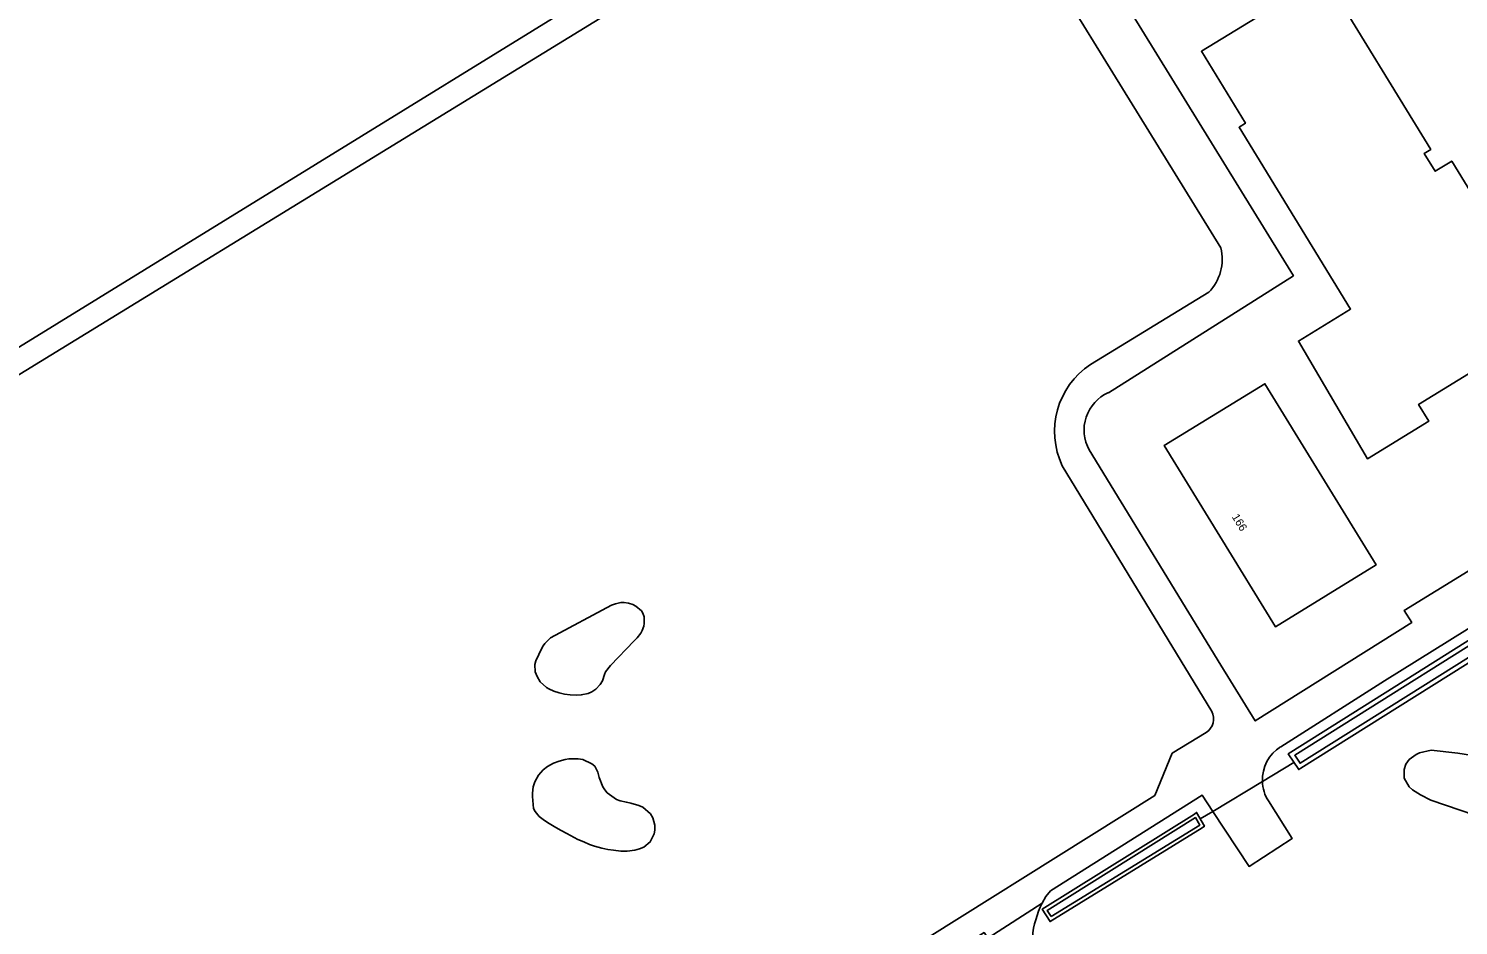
# Model space of a CAD drawing. Extents: x 156061 to 157804, y 383437 to 385640.
# Drawn here: x 157310.1 to 157488.8, y 384302.2 to 384414.3 of the extents above; entities that cross this region are included whole.
import ezdxf

# ---------------------------------------------------------------- set-up
doc = ezdxf.new("R2010")
doc.units = 0
for name, color, linetype in [('IMGEO_Duiker', 7, 'Continuous'), ('IMGEO_Groenvoorziening', 7, 'Continuous'), ('IMGEO_Oever', 7, 'Continuous'), ('IMGEO_Pand', 7, 'Continuous'), ('IMGEO_Pand_nummerreeks', 7, 'Continuous'), ('IMGEO_Parkeervlak_open', 7, 'Continuous'), ('IMGEO_Rijbaan_lokaal_open', 7, 'Continuous'), ('IMGEO_Terreindeel_zand', 7, 'Continuous'), ('IMGEO_Waterloop', 7, 'Continuous')]:
    doc.layers.add(name, color=color, linetype=linetype)

msp = doc.modelspace()

# ---------------------------------------------------------------- linework, layer by layer
at = {"layer": 'IMGEO_Duiker'}
msp.add_lwpolyline([(157468.24, 384322.62), (157464.32, 384320.24), (157458.11, 384316.49), (157456.56, 384315.56)], dxfattribs=at)
at = {"layer": 'IMGEO_Groenvoorziening'}
for points in [[(157422.9, 384440.97), (157244.99, 384331.9), (157233.07, 384324.81), (157231.44, 384327.44), (157263.86, 384346.91), (157291.7, 384363.94), (157433.08, 384451.02), (157463.89, 384469.64), (157500, 384491.86)], [(157459.14, 384386.91), (157426.43, 384439.93)], [(157434.04, 384438.87), (157468.2, 384383.43), (157445.07, 384368.81)], [(157442.82, 384372.34), (157457.62, 384381.36)], [(157442.68, 384361.66), (157459.13, 384334.77), (157463.42, 384327.8), (157482.98, 384340.1), (157482.05, 384341.61), (157490.03, 384346.53)], [(157457.99, 384328.99), (157439.3, 384359.67)], [(157500, 384345.51), (157479.57, 384332.82), (157466.6, 384324.58)], [(157422.28, 384264.72), (157416.27, 384274.39), (157438.11, 384288.09), (157430, 384300.64), (157429.54, 384301.35), (157347.95, 384250), (157322.66, 384234.08), (157320.89, 384236.78), (157341.5, 384250), (157450.86, 384318.47), (157453.06, 384323.75), (157457.3, 384326.36)], [(157490.88, 384316.01), (157485.38, 384317.89), (157484.06, 384318.55), (157483.07, 384319.2), (157482.68, 384319.57), (157482.05, 384320.66), (157482.02, 384321.74), (157482.26, 384322.38), (157482.67, 384322.96), (157483.52, 384323.61), (157483.93, 384323.81), (157485.4, 384324.14), (157488.74, 384323.78), (157491.37, 384323.35)], [(157465.07, 384317.8), (157468.04, 384313.11), (157462.66, 384309.61), (157458.11, 384316.49), (157456.79, 384318.5), (157437.84, 384306.57), (157437.24, 384305.85), (157436.8, 384305.03)]]:
    msp.add_lwpolyline(points, dxfattribs=at)
for points in [[(157500, 384378.16), (157500.4, 384377.5), (157500, 384377.25), (157483.83, 384367.34), (157485.12, 384365.26), (157477.44, 384360.55), (157468.81, 384375.27), (157475.33, 384379.26), (157461.4, 384401.99), (157462.2, 384402.49), (157456.69, 384411.48), (157472.06, 384420.9), (157485.36, 384399.22), (157484.54, 384398.72), (157485.91, 384396.48), (157487.98, 384397.76)], [(157500, 384341.28), (157469.14, 384321.89), (157468.85, 384321.71), (157467.54, 384323.67), (157467.87, 384323.89), (157500, 384344.09), (157567.48, 384386.23), (157568.22, 384386.06), (157568.84, 384385.18), (157568.87, 384384.42)], [(157478.53, 384347.29), (157465.94, 384339.56), (157452.04, 384362.21), (157464.63, 384369.94)], [(157382.85, 384334.74), (157382.23, 384333.92), (157382.1, 384333.6), (157381.83, 384332.82), (157381.55, 384332.33), (157381.01, 384331.77), (157380.5, 384331.42), (157380.06, 384331.23), (157379.18, 384331.05), (157378.58, 384331.03), (157377.79, 384331.07), (157377.1, 384331.16), (157376.41, 384331.31), (157375.76, 384331.51), (157375.13, 384331.8), (157374.83, 384331.98), (157374.07, 384332.68), (157373.66, 384333.33), (157373.44, 384333.93), (157373.38, 384334.83), (157373.5, 384335.29), (157373.87, 384336.11), (157374.09, 384336.56), (157374.42, 384337.17), (157374.63, 384337.46), (157375.35, 384338.18), (157382.95, 384342.26), (157383.48, 384342.45), (157384.14, 384342.61), (157384.56, 384342.61), (157385.11, 384342.52), (157385.65, 384342.33), (157386.01, 384342.15), (157386.7, 384341.57), (157386.9, 384341.26), (157387.05, 384340.81), (157387.06, 384339.96), (157387, 384339.62), (157386.82, 384339.09), (157386.64, 384338.76), (157386.19, 384338.19), (157385.8, 384337.79)], [(157373.85, 384321), (157374.41, 384321.67), (157374.97, 384322.11), (157375.74, 384322.51), (157376.43, 384322.77), (157377.2, 384322.96), (157377.65, 384323.04), (157378.79, 384323.07), (157379.37, 384322.97), (157380.51, 384322.45), (157380.87, 384322.15), (157381.26, 384321.39), (157381.43, 384320.72), (157381.87, 384319.57), (157382.14, 384319.17), (157382.43, 384318.82), (157383.6, 384317.96), (157384.05, 384317.8), (157384.83, 384317.64), (157385.39, 384317.53), (157386.37, 384317.24), (157386.87, 384317.01), (157387.84, 384316.18), (157388.12, 384315.7), (157388.37, 384314.77), (157388.38, 384314.13), (157388.32, 384313.7), (157387.82, 384312.67), (157387, 384312.04), (157386.48, 384311.81), (157385.89, 384311.64), (157384.92, 384311.52), (157384.12, 384311.54), (157383.24, 384311.63), (157382.53, 384311.74), (157381.76, 384311.91), (157380.85, 384312.16), (157380.24, 384312.37), (157379.5, 384312.67), (157378.78, 384313), (157378.29, 384313.24), (157377.38, 384313.71), (157376.69, 384314.09), (157376, 384314.48), (157375.2, 384314.97), (157374.59, 384315.36), (157373.93, 384315.87), (157373.42, 384316.46), (157373.21, 384316.87), (157373.08, 384318.37), (157373.1, 384318.78), (157373.2, 384319.58), (157373.38, 384320.17)], [(157437.78, 384302.72), (157436.8, 384304.27), (157455.82, 384316.16), (157456.1, 384316.36), (157457.08, 384314.64), (157456.81, 384314.44)]]:
    msp.add_lwpolyline(points, close=True, dxfattribs=at)
for centre, radius, start, end in [((157453.3, 384385.53), 6, 316.0189, 13.3207), ((157448.38, 384363.97), 10.04, 123.5766, 205.3383), ((157447.14, 384364.15), 5.11, 113.9447, 209.1133), ((157456.24, 384328.05), 1.99, 302.1109, 28.211), ((157469.24, 384320.42), 4.93, 122.4518, 181.9995), ((157469.25, 384320.42), 4.94, 182.0776, 212.1015), ((157447.84, 384299.56), 12.33, 153.6448, 174.3328)]:
    msp.add_arc(centre, radius, start, end, dxfattribs=at)
at = {"layer": 'IMGEO_Oever'}
for points in [[(157568.87, 384384.42), (157568.84, 384385.18), (157568.22, 384386.06), (157567.48, 384386.23), (157500, 384344.09), (157467.87, 384323.89), (157467.54, 384323.67), (157468.85, 384321.71), (157469.14, 384321.89), (157500, 384341.28)], [(157567.37, 384385.48), (157567.83, 384385.42), (157568.11, 384385), (157568.11, 384384.62), (157499.69, 384341.77), (157469.02, 384322.5), (157468.35, 384323.51), (157500.31, 384343.59)], [(157456.81, 384314.44), (157457.08, 384314.64), (157456.1, 384316.36), (157455.82, 384316.16), (157436.8, 384304.27), (157437.78, 384302.72)], [(157437.93, 384303.34), (157437.43, 384304.12), (157455.95, 384315.71), (157456.48, 384314.78)]]:
    msp.add_lwpolyline(points, close=True, dxfattribs=at)
at = {"layer": 'IMGEO_Pand'}
for points in [[(157477.44, 384360.55), (157485.12, 384365.26), (157483.83, 384367.34), (157500, 384377.25), (157500.4, 384377.5), (157500, 384378.16), (157487.98, 384397.76), (157485.91, 384396.48), (157484.54, 384398.72), (157485.36, 384399.22), (157472.06, 384420.9), (157456.69, 384411.48), (157462.2, 384402.49), (157461.4, 384401.99), (157475.33, 384379.26), (157468.81, 384375.27)], [(157465.94, 384339.56), (157478.53, 384347.29), (157464.63, 384369.94), (157452.04, 384362.21)]]:
    msp.add_lwpolyline(points, close=True, dxfattribs=at)
at = {"layer": 'IMGEO_Parkeervlak_open'}
msp.add_lwpolyline([(157436.8, 384305.03), (157430, 384300.64), (157438.11, 384288.09), (157416.27, 384274.39), (157422.28, 384264.72)], dxfattribs=at)
msp.add_arc((157447.84, 384299.56), 12.33, 153.6448, 174.3328, dxfattribs=at)
at = {"layer": 'IMGEO_Rijbaan_lokaal_open'}
for points in [[(157436.45, 384449.02), (157483.73, 384477.95), (157500, 384488.13), (157519.16, 384500), (157576.02, 384534.59), (157575.65, 384535.14), (157574.2, 384537.32), (157551.17, 384523.14), (157550.12, 384524.27), (157535.92, 384547.39), (157533.05, 384545.65), (157542.26, 384531.48), (157547.06, 384523.53), (157546.9, 384520.27), (157513.14, 384500), (157500, 384491.86), (157463.89, 384469.64), (157433.08, 384451.02), (157291.7, 384363.94), (157263.86, 384346.91), (157231.44, 384327.44), (157233.07, 384324.81), (157244.99, 384331.9), (157422.9, 384440.97)], [(157426.29, 384440.16), (157426.43, 384439.93), (157459.14, 384386.91)], [(157468.2, 384383.43), (157434.04, 384438.87)], [(157466.6, 384324.58), (157479.57, 384332.82), (157500, 384345.51), (157542.83, 384372.24), (157576.48, 384393.45), (157639.23, 384432.54), (157636.71, 384433.54), (157636.04, 384434.05), (157635.86, 384434.29), (157629.02, 384430.08), (157500, 384349.24), (157495.24, 384346.26)], [(157445.07, 384368.81), (157468.2, 384383.43)], [(157457.62, 384381.36), (157442.82, 384372.34)], [(157490.03, 384346.53), (157482.05, 384341.61), (157482.98, 384340.1), (157463.42, 384327.8), (157459.13, 384334.77), (157442.68, 384361.66)], [(157439.3, 384359.67), (157457.99, 384328.99)], [(157457.3, 384326.36), (157453.06, 384323.75), (157450.86, 384318.47), (157341.5, 384250), (157320.89, 384236.78), (157322.66, 384234.08), (157347.95, 384250), (157429.54, 384301.35), (157430, 384300.64), (157436.8, 384305.03), (157437.24, 384305.85), (157437.84, 384306.57), (157456.79, 384318.5), (157458.11, 384316.49), (157462.66, 384309.61), (157468.04, 384313.11), (157465.07, 384317.8)]]:
    msp.add_lwpolyline(points, dxfattribs=at)
for centre, radius, start, end in [((157453.3, 384385.53), 6, 316.0189, 13.3207), ((157448.38, 384363.97), 10.04, 123.5766, 205.3383), ((157447.14, 384364.15), 5.11, 113.9447, 209.1133), ((157456.24, 384328.05), 1.99, 302.1109, 28.211), ((157469.24, 384320.42), 4.93, 122.4518, 181.9995), ((157469.25, 384320.42), 4.94, 182.0776, 212.1015)]:
    msp.add_arc(centre, radius, start, end, dxfattribs=at)
at = {"layer": 'IMGEO_Terreindeel_zand'}
for points in [[(157382.85, 384334.74), (157385.8, 384337.79), (157386.19, 384338.19), (157386.64, 384338.76), (157386.82, 384339.09), (157387, 384339.62), (157387.06, 384339.96), (157387.05, 384340.81), (157386.9, 384341.26), (157386.7, 384341.57), (157386.01, 384342.15), (157385.65, 384342.33), (157385.11, 384342.52), (157384.56, 384342.61), (157384.14, 384342.61), (157383.48, 384342.45), (157382.95, 384342.26), (157375.35, 384338.18), (157374.63, 384337.46), (157374.42, 384337.17), (157374.09, 384336.56), (157373.87, 384336.11), (157373.5, 384335.29), (157373.38, 384334.83), (157373.44, 384333.93), (157373.66, 384333.33), (157374.07, 384332.68), (157374.83, 384331.98), (157375.13, 384331.8), (157375.76, 384331.51), (157376.41, 384331.31), (157377.1, 384331.16), (157377.79, 384331.07), (157378.58, 384331.03), (157379.18, 384331.05), (157380.06, 384331.23), (157380.5, 384331.42), (157381.01, 384331.77), (157381.55, 384332.33), (157381.83, 384332.82), (157382.1, 384333.6), (157382.23, 384333.92)], [(157373.85, 384321), (157373.38, 384320.17), (157373.2, 384319.58), (157373.1, 384318.78), (157373.08, 384318.37), (157373.21, 384316.87), (157373.42, 384316.46), (157373.93, 384315.87), (157374.59, 384315.36), (157375.2, 384314.97), (157376, 384314.48), (157376.69, 384314.09), (157377.38, 384313.71), (157378.29, 384313.24), (157378.78, 384313), (157379.5, 384312.67), (157380.24, 384312.37), (157380.85, 384312.16), (157381.76, 384311.91), (157382.53, 384311.74), (157383.24, 384311.63), (157384.12, 384311.54), (157384.92, 384311.52), (157385.89, 384311.64), (157386.48, 384311.81), (157387, 384312.04), (157387.82, 384312.67), (157388.32, 384313.7), (157388.38, 384314.13), (157388.37, 384314.77), (157388.12, 384315.7), (157387.84, 384316.18), (157386.87, 384317.01), (157386.37, 384317.24), (157385.39, 384317.53), (157384.83, 384317.64), (157384.05, 384317.8), (157383.6, 384317.96), (157382.43, 384318.82), (157382.14, 384319.17), (157381.87, 384319.57), (157381.43, 384320.72), (157381.26, 384321.39), (157380.87, 384322.15), (157380.51, 384322.45), (157379.37, 384322.97), (157378.79, 384323.07), (157377.65, 384323.04), (157377.2, 384322.96), (157376.43, 384322.77), (157375.74, 384322.51), (157374.97, 384322.11), (157374.41, 384321.67)]]:
    msp.add_lwpolyline(points, close=True, dxfattribs=at)
msp.add_lwpolyline([(157491.37, 384323.35), (157488.74, 384323.78), (157485.4, 384324.14), (157483.93, 384323.81), (157483.52, 384323.61), (157482.67, 384322.96), (157482.26, 384322.38), (157482.02, 384321.74), (157482.05, 384320.66), (157482.68, 384319.57), (157483.07, 384319.2), (157484.06, 384318.55), (157485.38, 384317.89), (157490.88, 384316.01)], dxfattribs=at)
at = {"layer": 'IMGEO_Waterloop'}
for points in [[(157567.37, 384385.48), (157500.31, 384343.59), (157468.35, 384323.51), (157469.02, 384322.5), (157499.69, 384341.77), (157568.11, 384384.62), (157568.11, 384385), (157567.83, 384385.42)], [(157437.93, 384303.34), (157456.48, 384314.78), (157455.95, 384315.71), (157437.43, 384304.12)]]:
    msp.add_lwpolyline(points, close=True, dxfattribs=at)

# ---------------------------------------------------------------- texts
at = {"layer": 'IMGEO_Pand_nummerreeks'}
msp.add_text('166', height=1, rotation=301.5461, dxfattribs=at).set_placement((157460.46, 384353.3))

doc.saveas('drawing.dxf')
